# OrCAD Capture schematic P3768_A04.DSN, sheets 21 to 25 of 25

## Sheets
21 0004_SODIMM Connector 1_3: size Custom
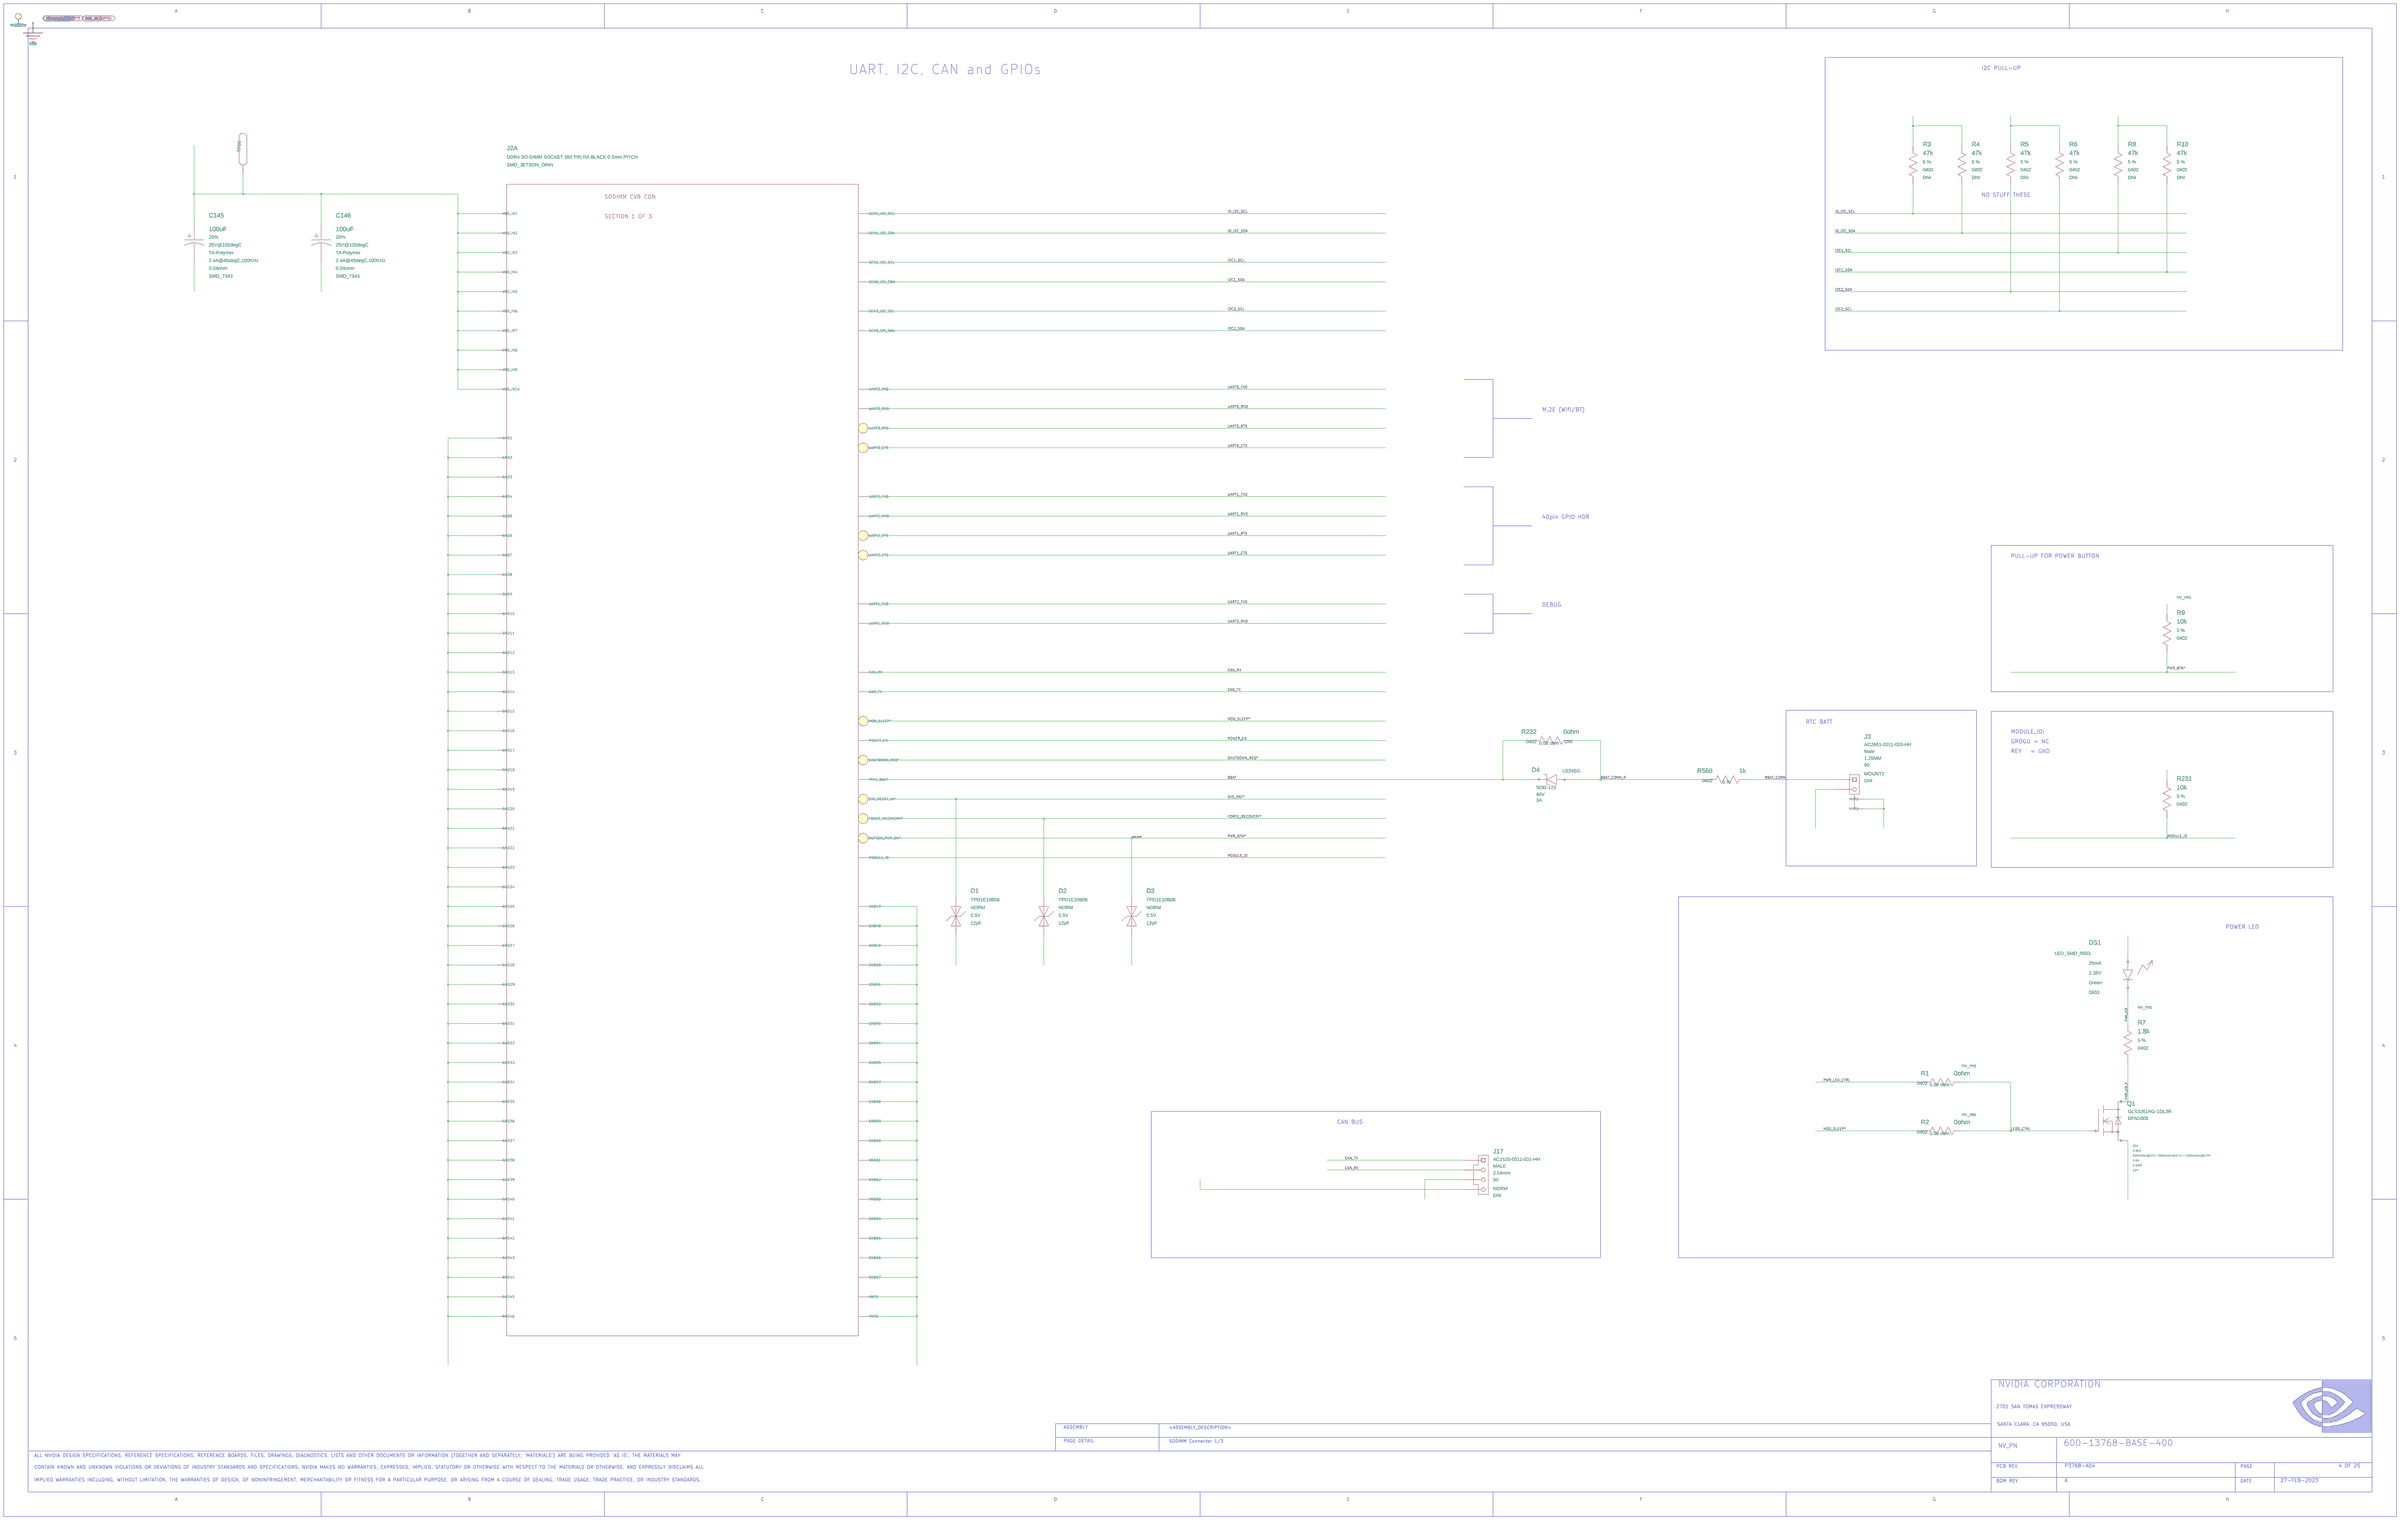
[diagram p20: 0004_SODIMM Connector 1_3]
22 0003_Power Tree
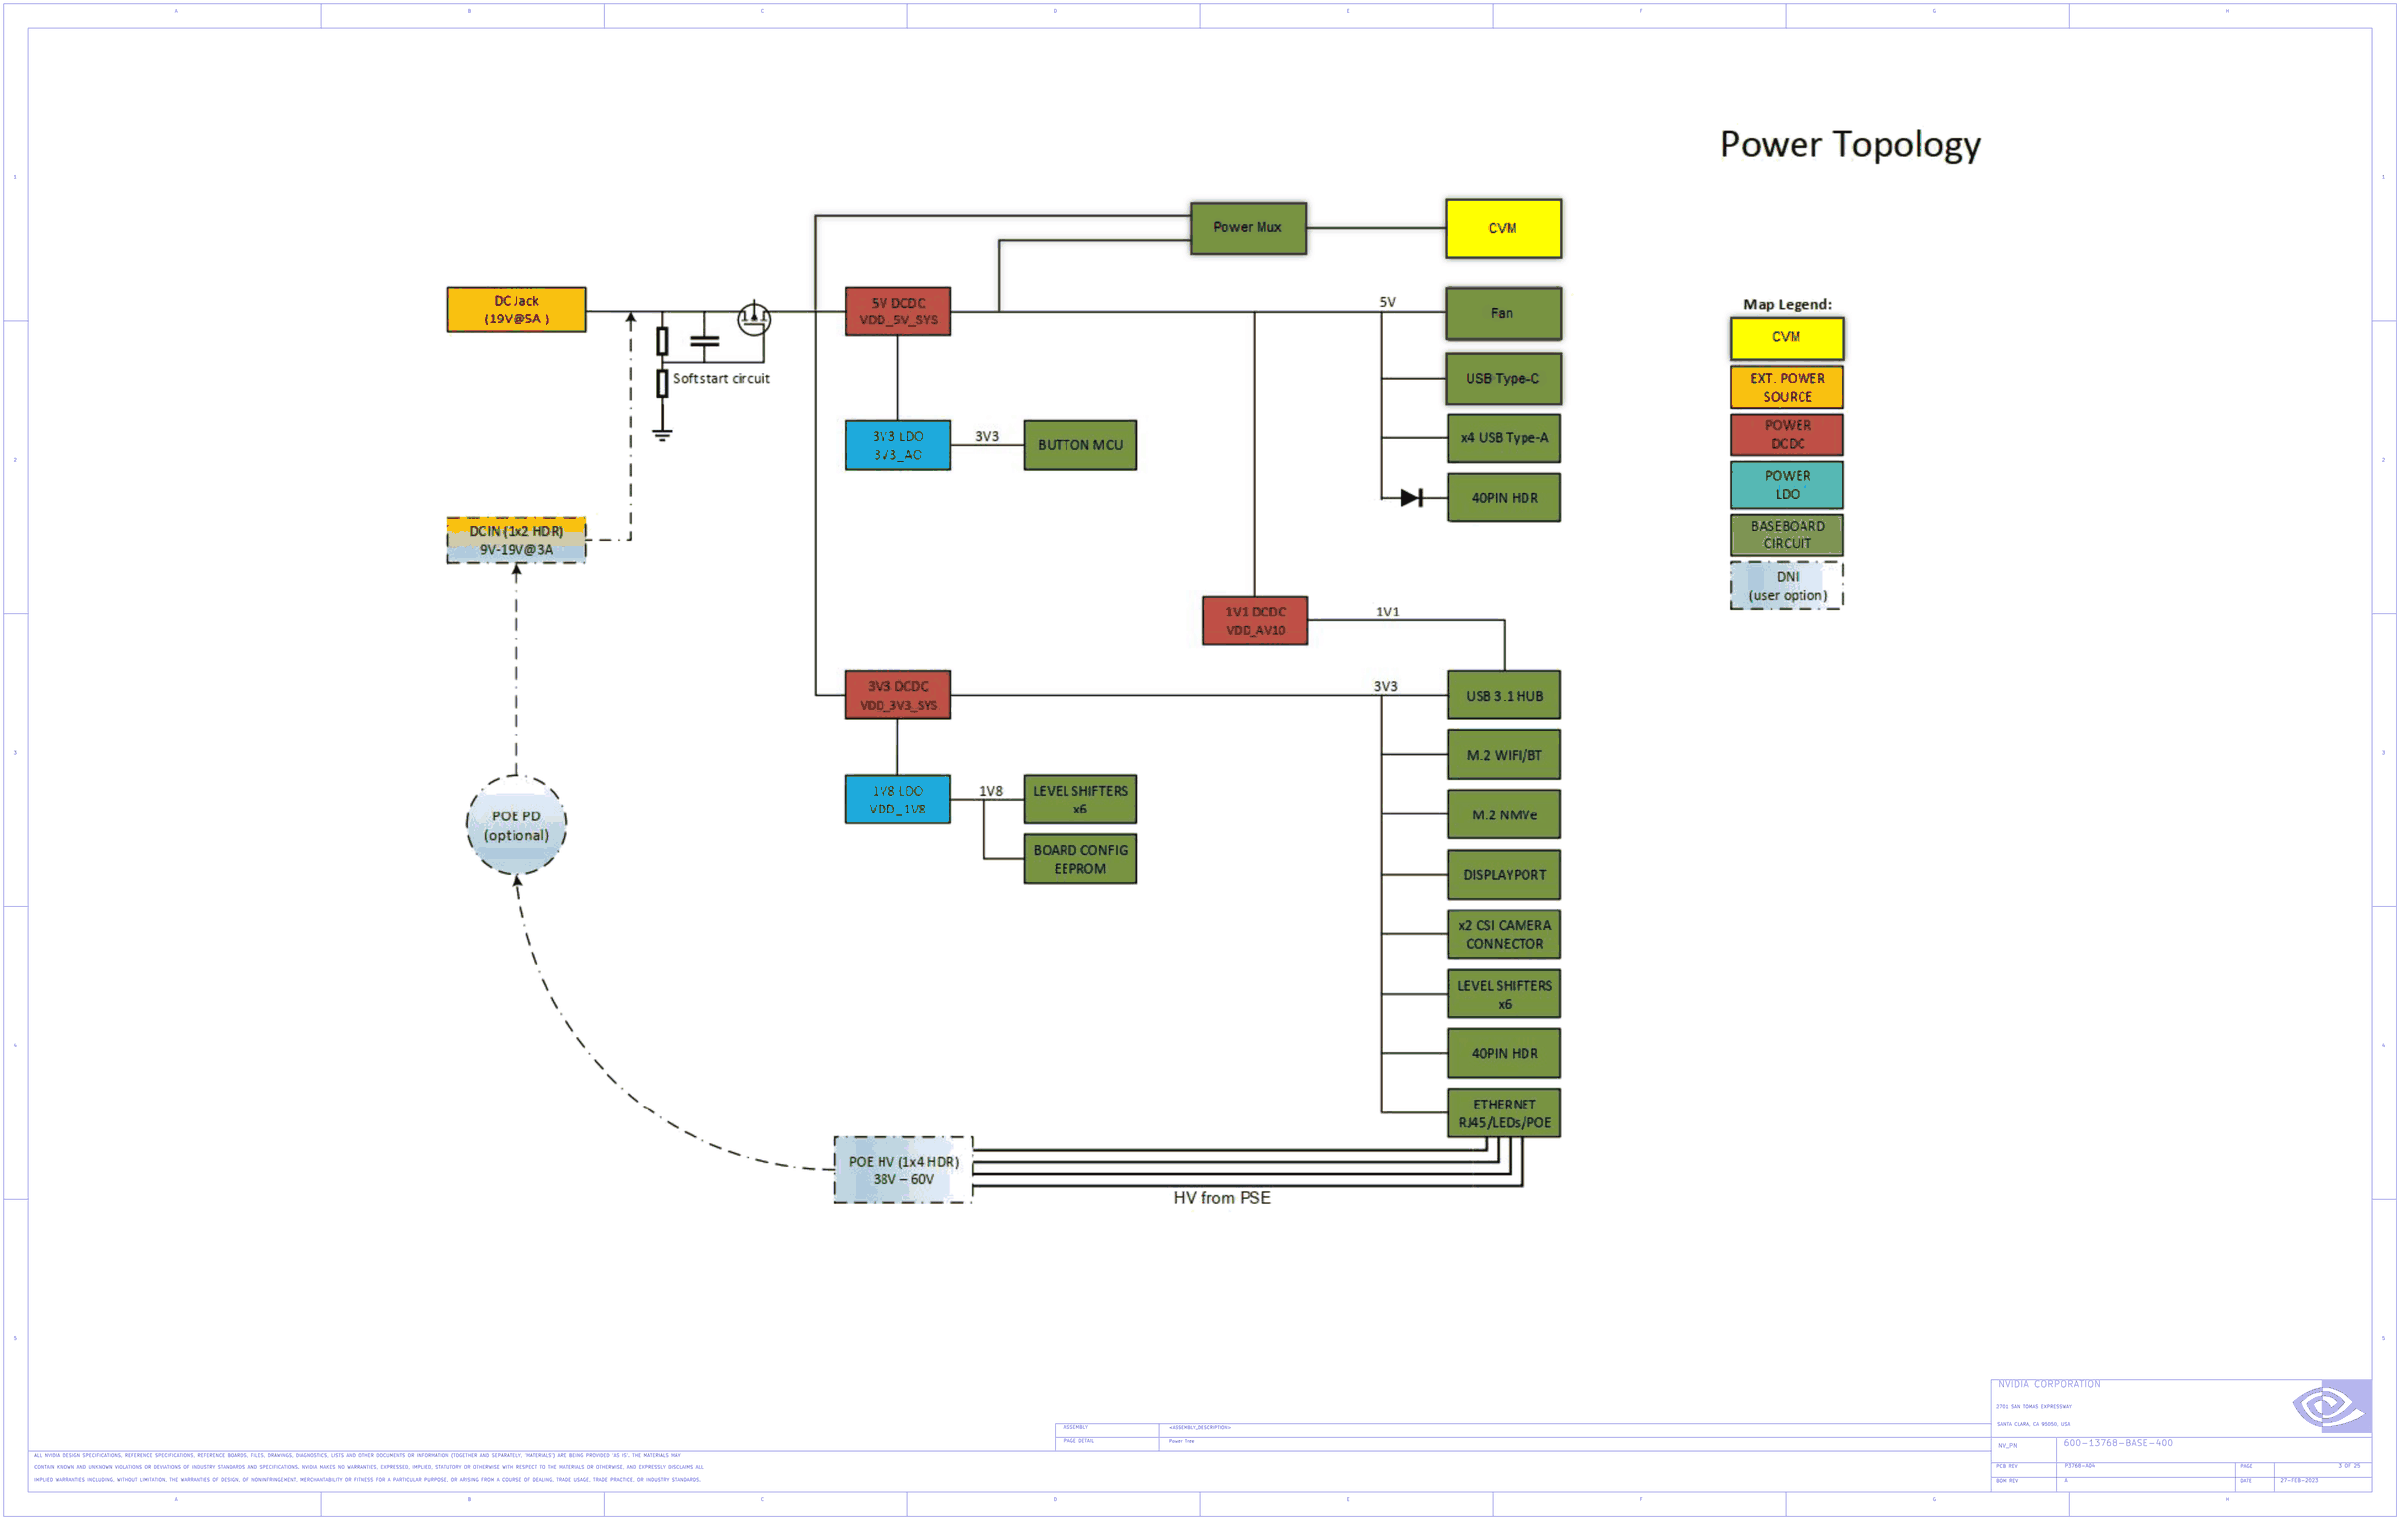
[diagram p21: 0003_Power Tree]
23 0002_Block Diagram
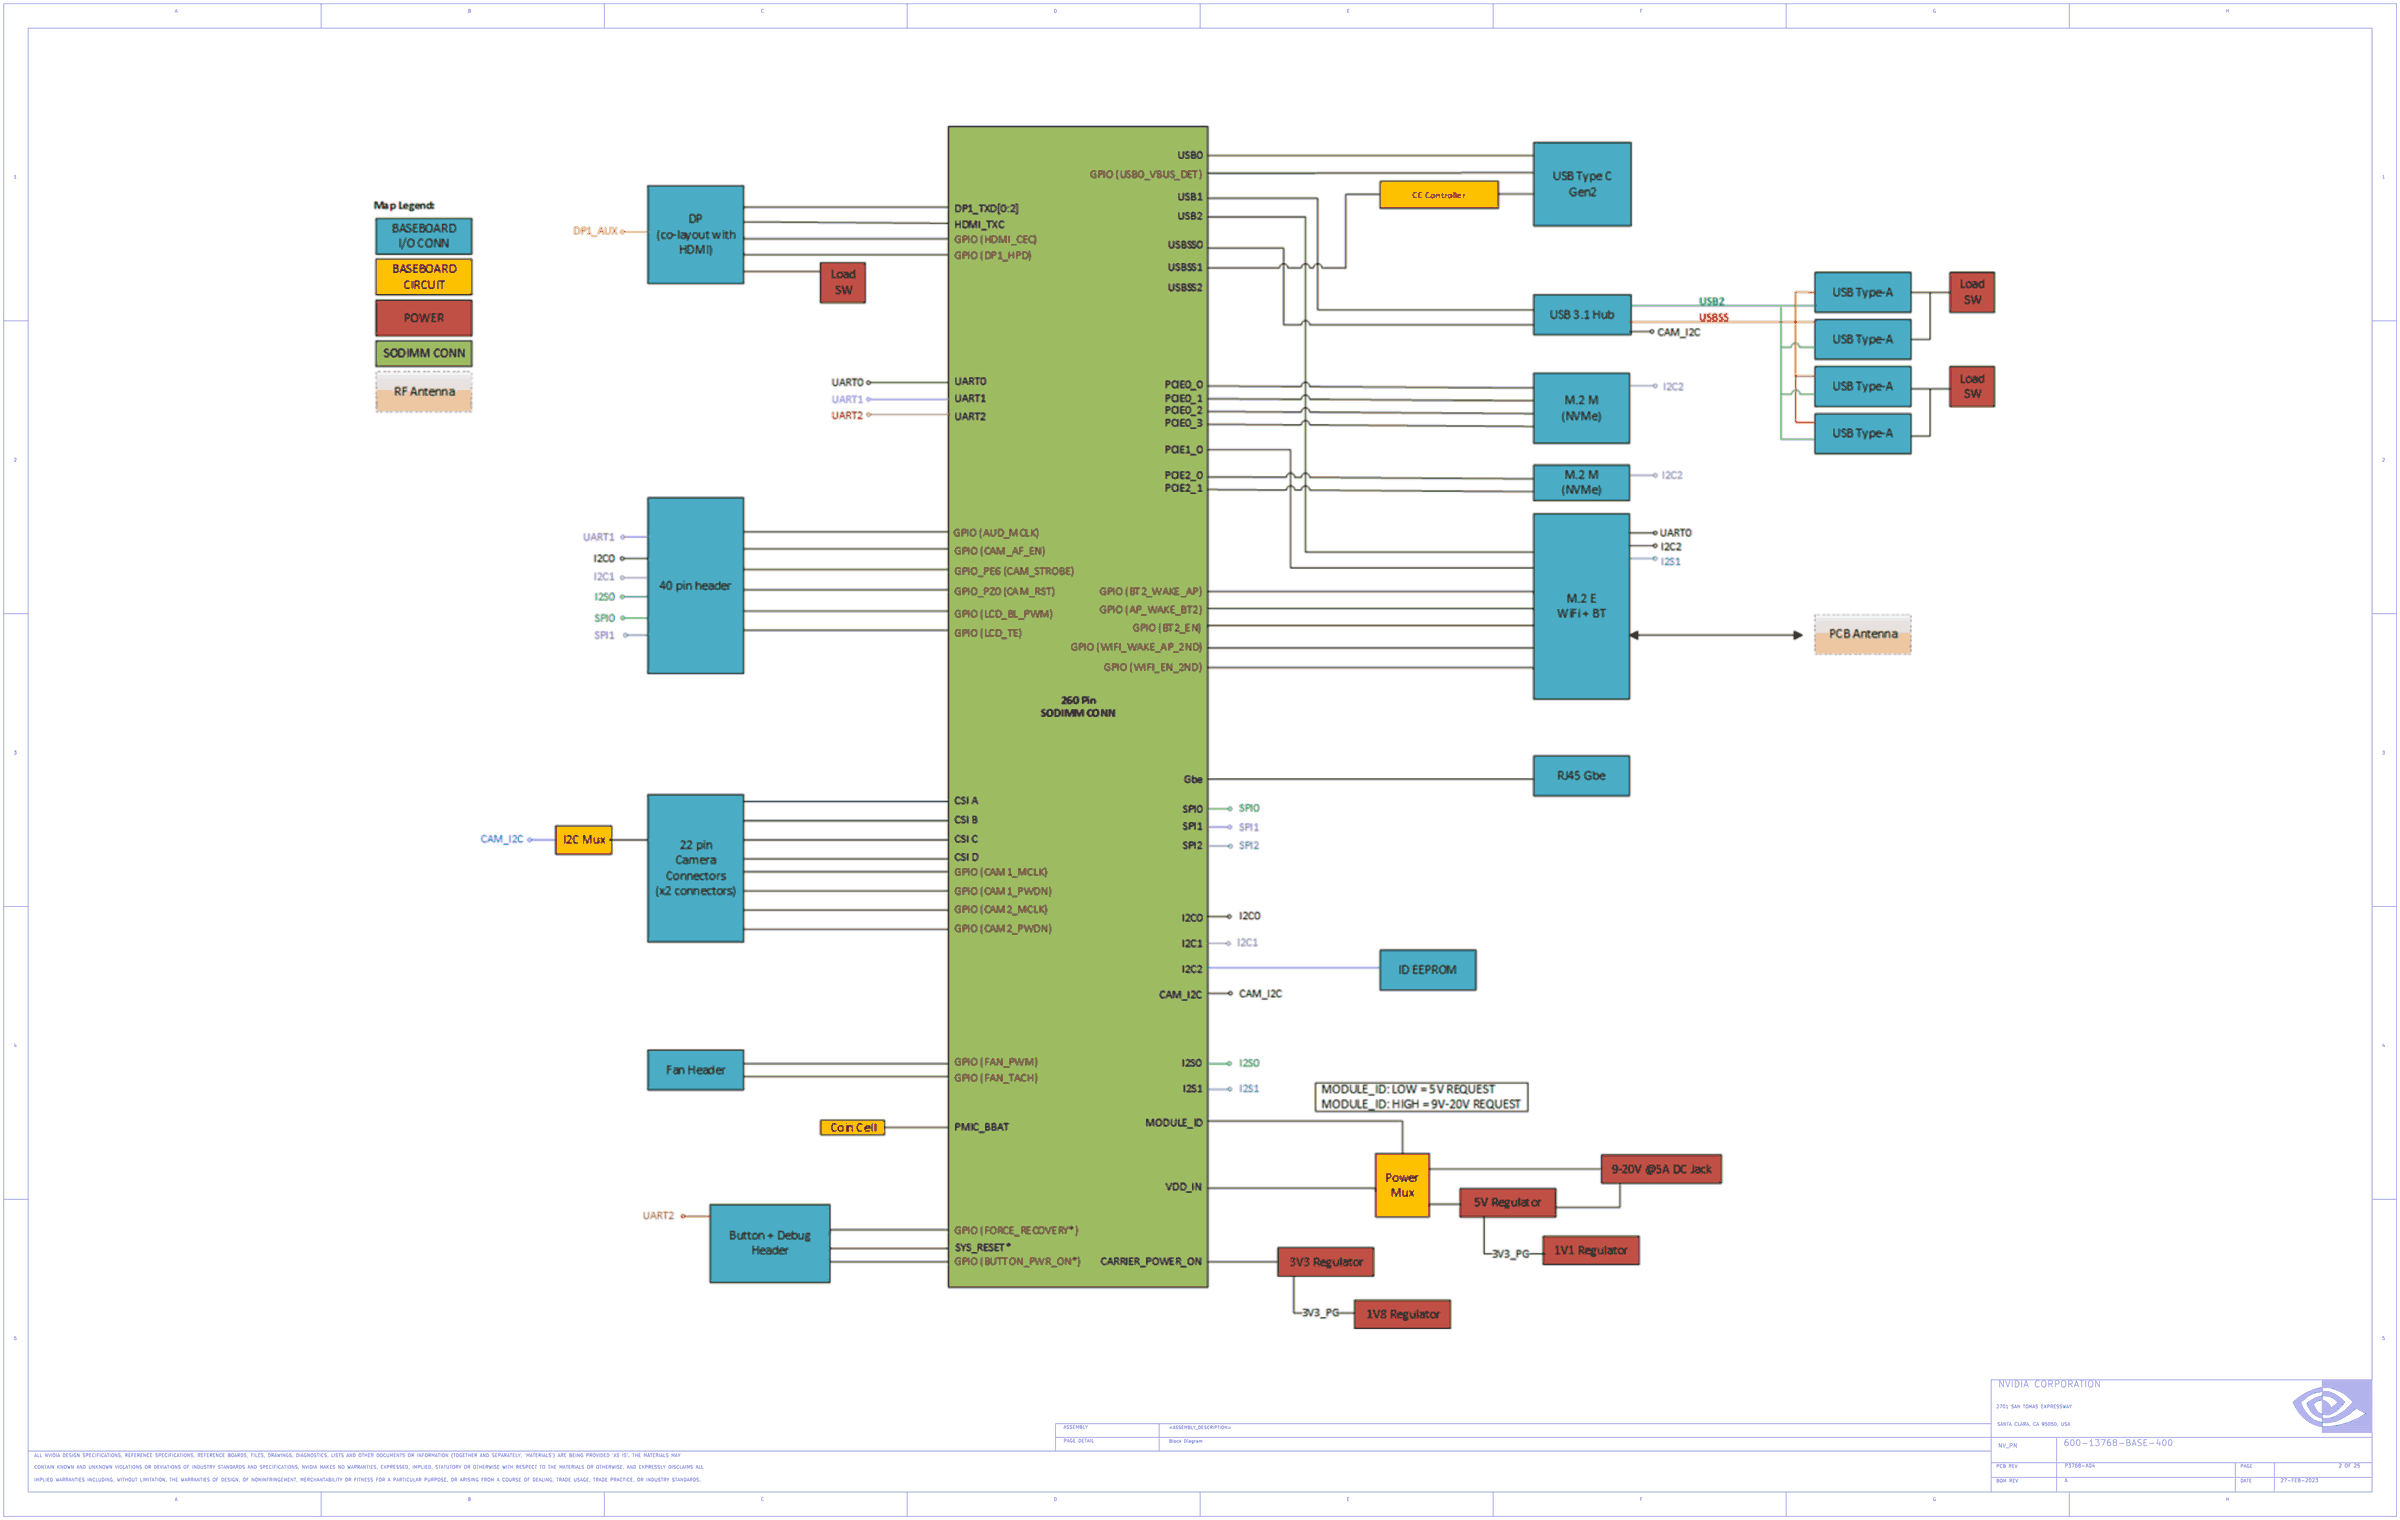
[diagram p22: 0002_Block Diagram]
24 0001_Table of Contents
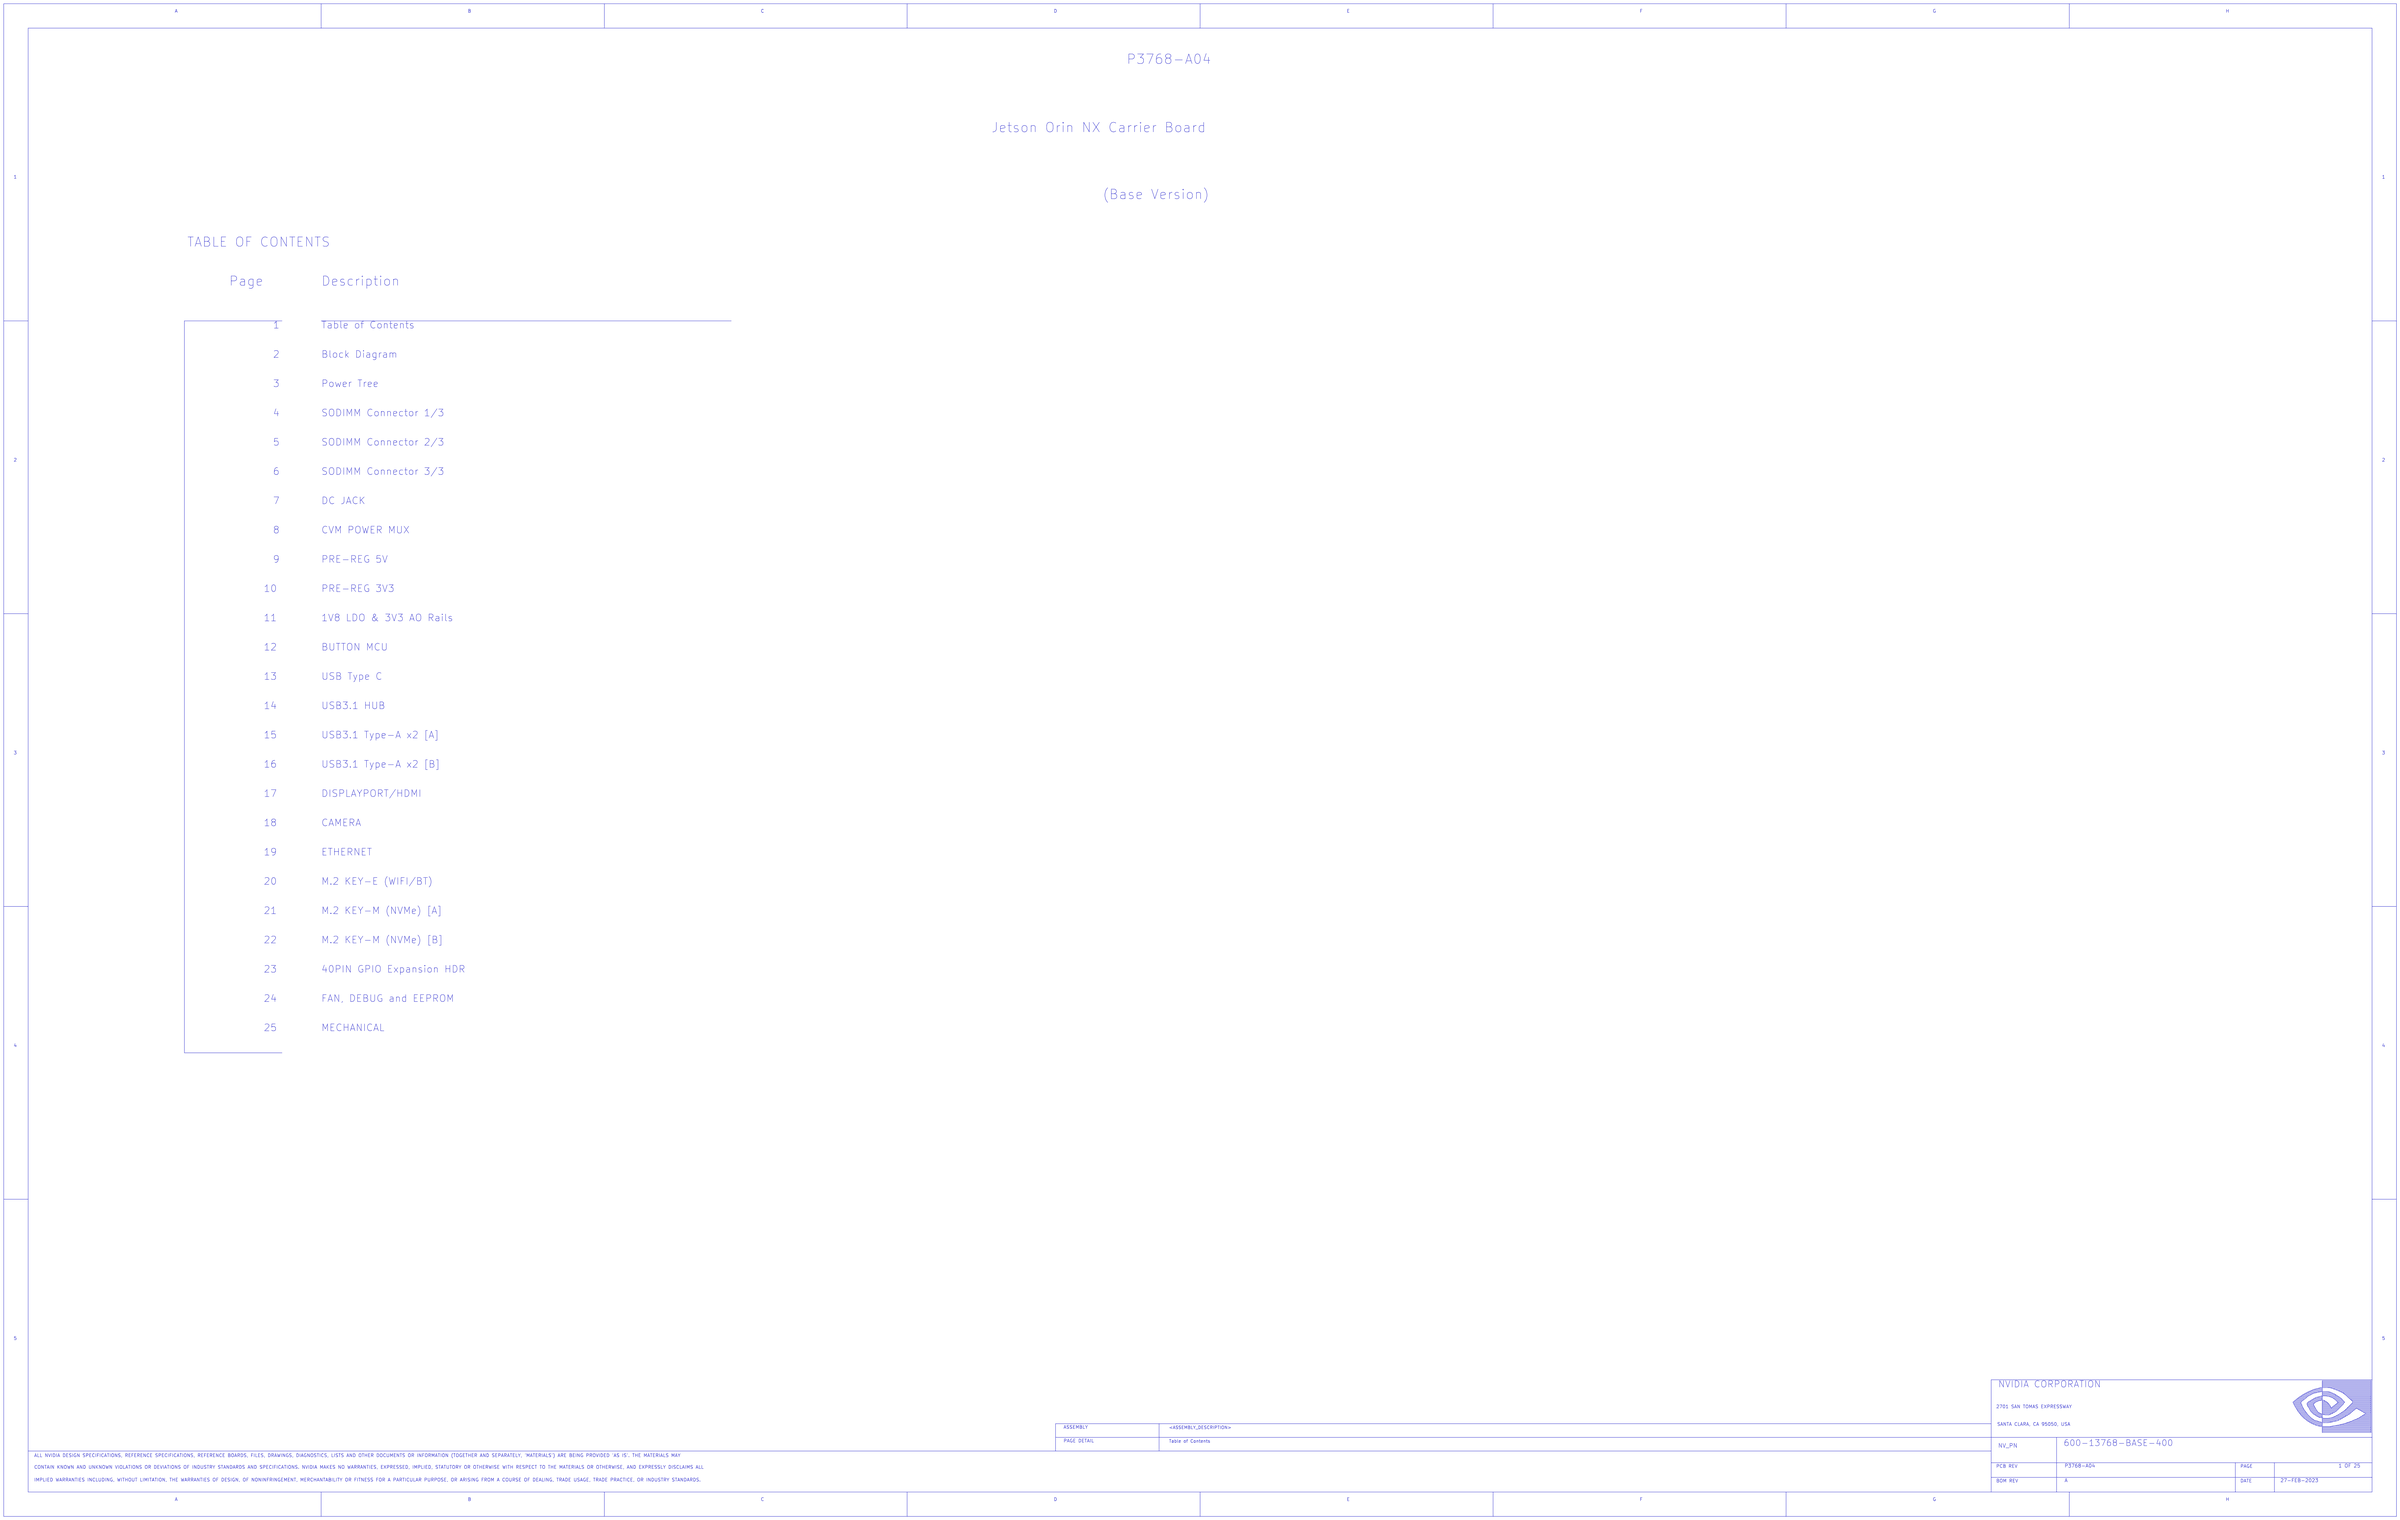
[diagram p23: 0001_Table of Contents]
25 0025_MECHANICAL: size Custom
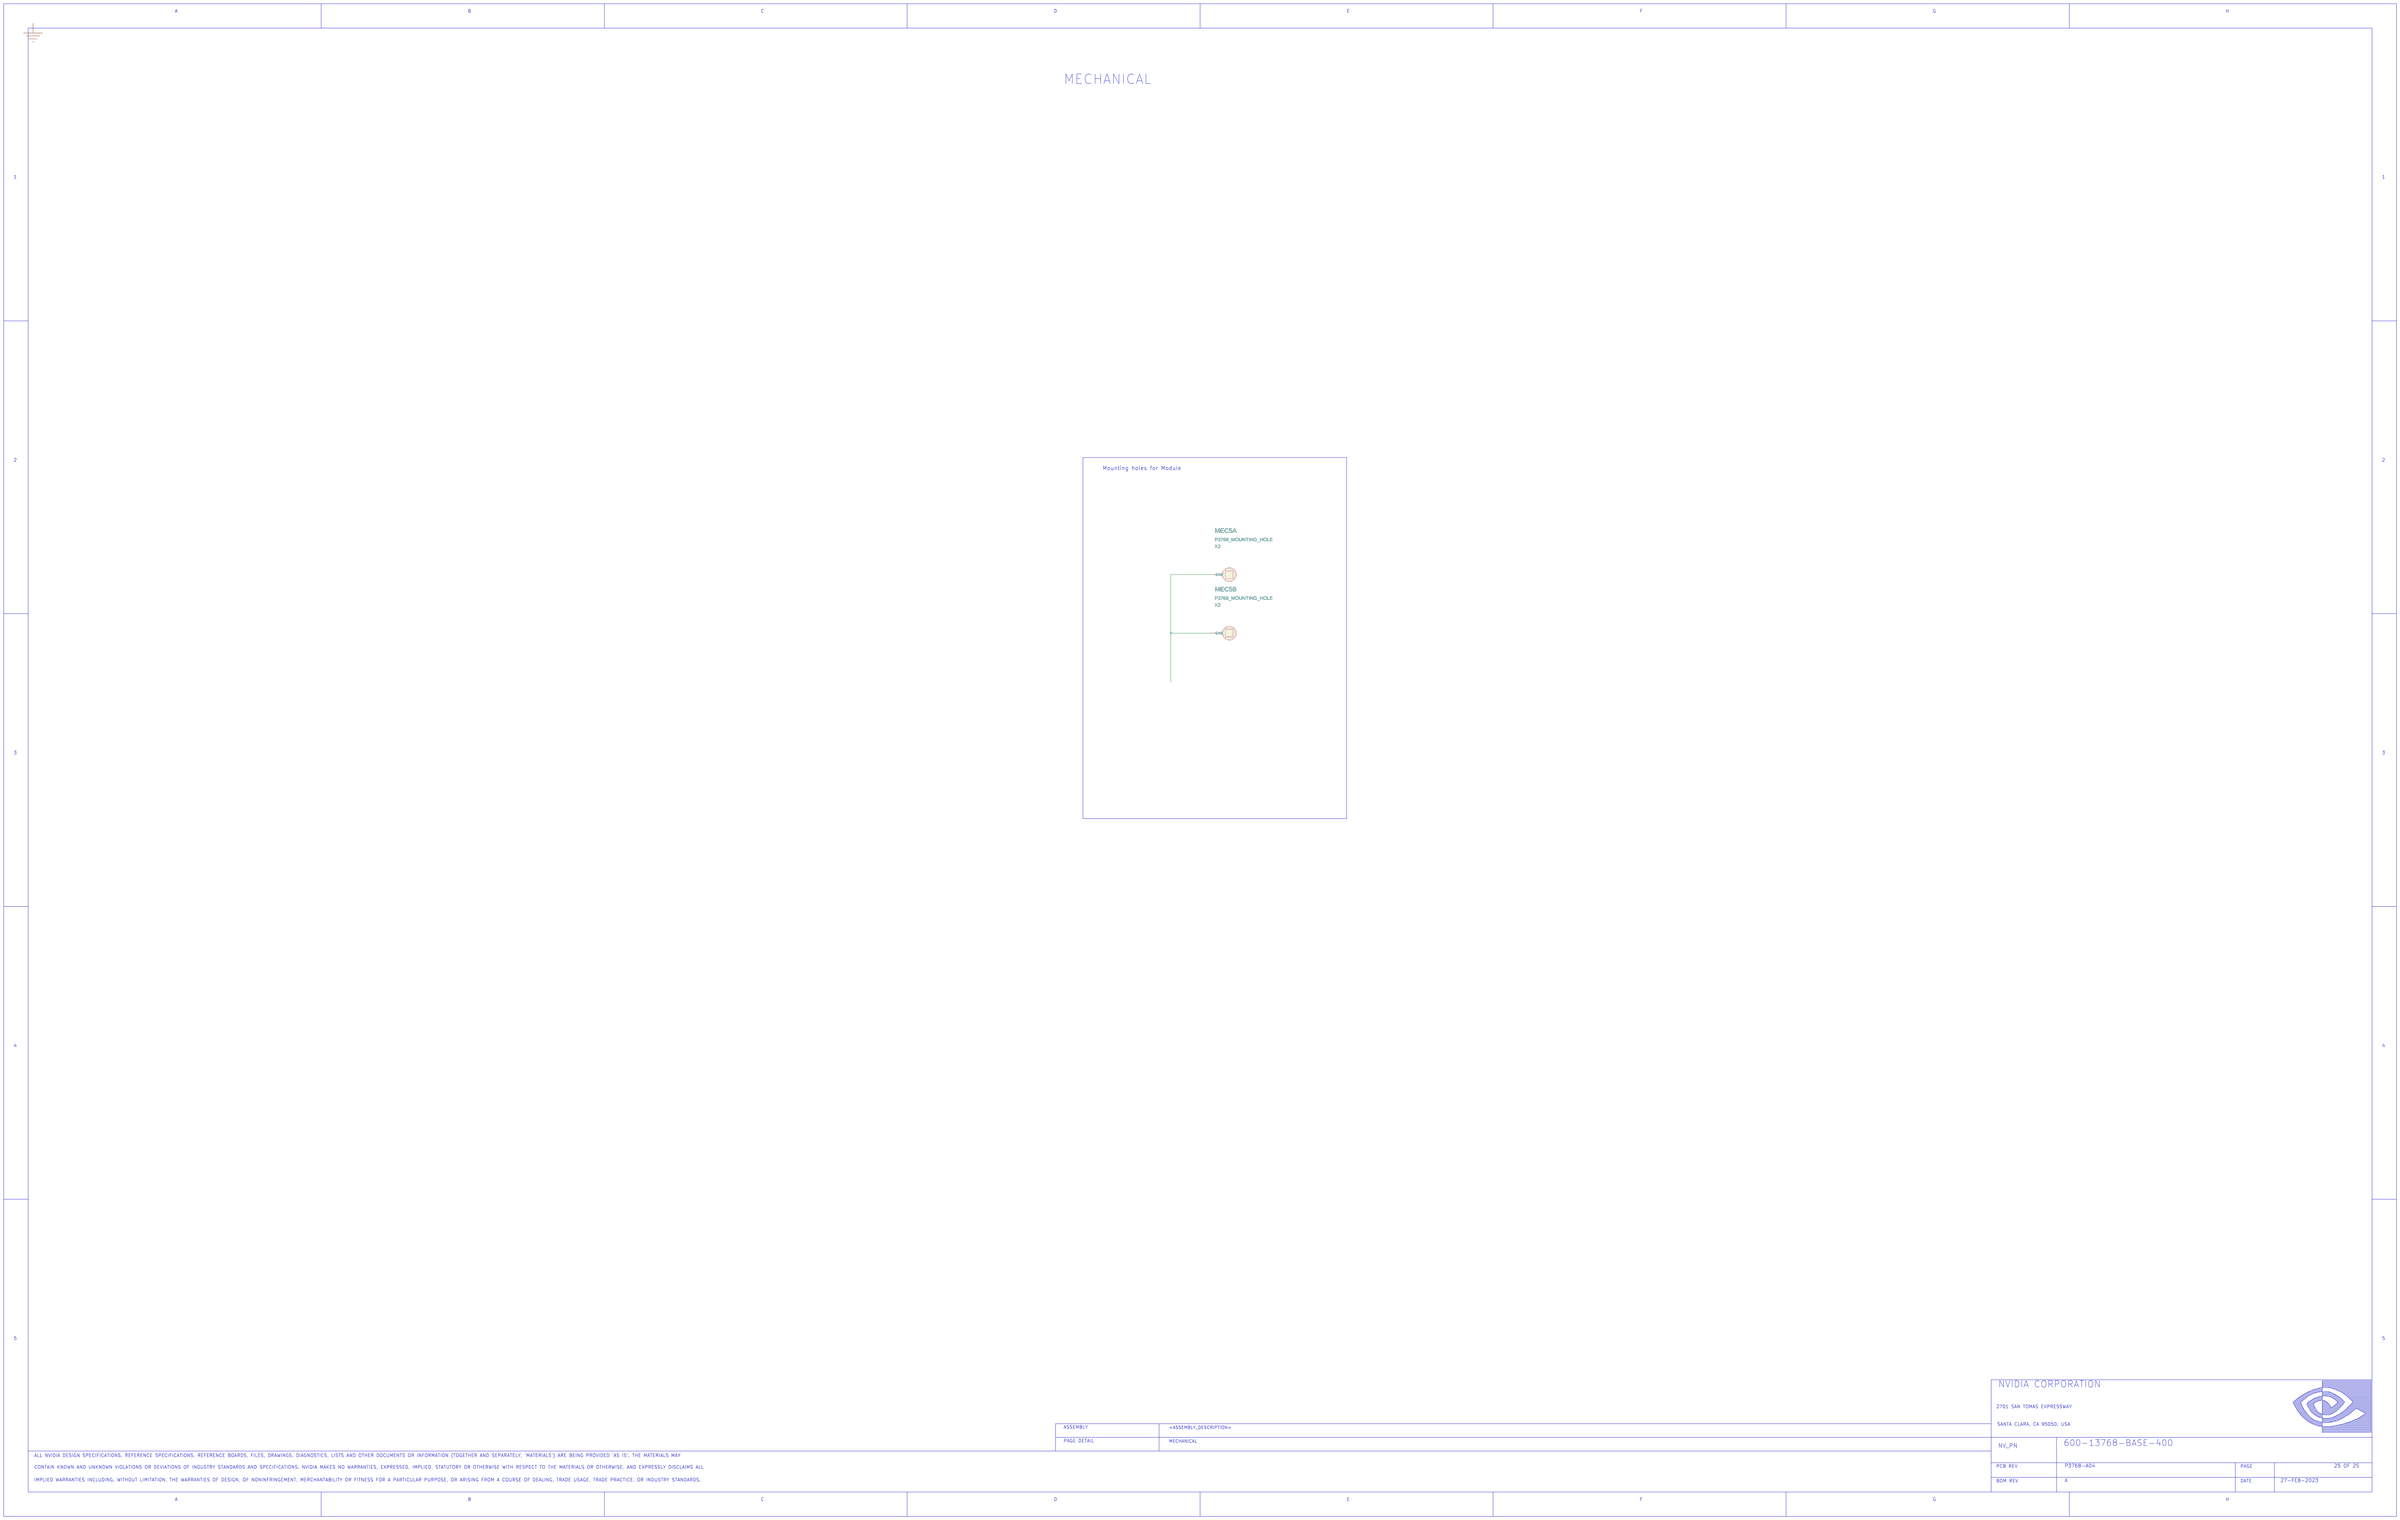
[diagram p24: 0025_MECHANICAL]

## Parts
sheet 0004_SODIMM Connector 1_3
C145  100uF  [CAP_SMD_7343]
C146  100uF  [CAP_SMD_7343]
D1  D_ESD  [DIODE_SMD_010X060]
D2  D_ESD  [DIODE_SMD_010X060]
D3  D_ESD  [DIODE_SMD_010X060]
D4  D_SCHOTTKY  [DIODE_SMD_SOD123]
DS1  LED  [LED_SMD_0603_ST]
J3  HDR_1X2  [CON_MISC_002_SMD_RA_M_P013_WTB_B]
J17  HDR_1X4  [CON_HDR_001X004_TH_RA_M_P025_B]
Q1  Q_FET_N_ENH  [DFET_003_SMD_010X006_B]
R1  0ohm  [0402]
R2  0ohm  [0402]
R3  47k  [0402]
R4  47k  [0402]
R5  47k  [0402]
R6  47k  [0402]
R7  1.8k  [0402]
R8  47k  [0402]
R9  10k  [0402]
R10  47k  [0402]
R222  0ohm  [0402]
R231  10k  [0402]
R560  1k  [0402]
TP55  LABTESTPOINT  [LTPT071C125D]
sheet 0006_SODIMM Connector 3_3
J2  CON_SODIMM_260  [CON_SODIMM_260_SMT_RA_F_P005]  (sections A,B,C)
sheet 0025_MECHANICAL
MEC5  MOUNTING_HOLE  [MECH_RECT_01000X00790_HOLES_C]  (sections A,B)

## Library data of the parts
C145 = C_POL: ASSEMBLY: CVB_CONN; CDS_LIB: discrete; CDS_PART_NAME: C_POL_SMD_7343-100UF,TA-POLYMER,20%,25V@105DEGC,0.04OHM,9.999UH,2.4A@45DEGC,100KHZ,032-0796-000; CDS_PHYS_PART_NAME: C_POL_SMD_7343-100UF,TA-POLYMER,20%,25V@105DEGC,0.04OHM,9.999UH,2.4A@45DEGC,100KHZ,032-0796-000-032-0796-000,100UF; CDS_SEC: 1; DEVICE_TYPENAME: C_POL_SMD_7343-100UFTA-POLYMER2025V105DEGC004OHM9999UH24A45DEGC100KHZ032-0796-000-032-0796-000100UF; DRAWING: @P3768_A04_LIB.P3768_A04(SCH_1):PAGE4; ESL: 9.999uH; ESR: 0.04ohm; MAT: TA-Polymer; MAX_VOLTAGE: 25V@105degC; NV_PN: 032-0796-000; PACK_TYPE: SMD_7343; PATH: I146; PHYS_PAGE: 4; RIPPLE_CURRENT: 2.4A@45degC,100KHz; ROT: 0; SEC: 1; SIGNAL_MODEL: nv_capp; TOL: 20%; VER: 1; XY: (-11150,6400)
C146 = C_POL: ASSEMBLY: CVB_CONN; CDS_LIB: discrete; CDS_PART_NAME: C_POL_SMD_7343-100UF,TA-POLYMER,20%,25V@105DEGC,0.04OHM,9.999UH,2.4A@45DEGC,100KHZ,032-0796-000; CDS_PHYS_PART_NAME: C_POL_SMD_7343-100UF,TA-POLYMER,20%,25V@105DEGC,0.04OHM,9.999UH,2.4A@45DEGC,100KHZ,032-0796-000-032-0796-000,100UF; CDS_SEC: 1; DEVICE_TYPENAME: C_POL_SMD_7343-100UFTA-POLYMER2025V105DEGC004OHM9999UH24A45DEGC100KHZ032-0796-000-032-0796-000100UF; DRAWING: @P3768_A04_LIB.P3768_A04(SCH_1):PAGE4; ESL: 9.999uH; ESR: 0.04ohm; MAT: TA-Polymer; MAX_VOLTAGE: 25V@105degC; NV_PN: 032-0796-000; PACK_TYPE: SMD_7343; PATH: I147; PHYS_PAGE: 4; RIPPLE_CURRENT: 2.4A@45degC,100KHz; ROT: 0; SEC: 1; SIGNAL_MODEL: nv_capp; TOL: 20%; VER: 1; XY: (-10500,6400)
D1 = D_ESD: ASSEMBLY: CVB_CONN; BREAKDOWN_VOLTAGE_MIN_TYP: 6V; CAPACITANCE_MAX_TYP: 12pF; CDS_LIB: discrete; CDS_PART_NAME: D_ESD_NORM-TPD1E10B06,1 LINE,BI-DIRECTIONAL,5.5V,0.1UA,6V,10V@1A,12PF,090-0243-000; CDS_PHYS_PART_NAME: D_ESD_NORM-TPD1E10B06,1 LINE,BI-DIRECTIONAL,5.5V,0.1UA,6V,10V@1A,12PF,090-0243-000-090-0243-000; CDS_SEC: 1; CLAMPING_VOLTAGE: 10V@1A; CONFIGURATION: 1 Line; DEVICE_TYPENAME: D_ESD_NORM-TPD1E10B061LINEBI-DIRECTIONAL55V01UA6V10V1A12PF090-0243-000-090-0243-000; DRAWING: @P3768_A04_LIB.P3768_A04(SCH_1):PAGE4; MAX_REVERSE_LEAKAGE_CURRENT: 0.1uA; MAX_REVERSE_VOLTAGE: 5.5V; NV_NAME: TPD1E10B06; NV_PN: 090-0243-000; PACK_TYPE: NORM; PATH: I54; PHYS_PAGE: 4; POLARITY: Bi-Directional; ROT: 0; SEC: 1; VER: 2; XY: (-7250,2950)
D2 = D_ESD: ASSEMBLY: CVB_CONN; BREAKDOWN_VOLTAGE_MIN_TYP: 6V; CAPACITANCE_MAX_TYP: 12pF; CDS_LIB: discrete; CDS_PART_NAME: D_ESD_NORM-TPD1E10B06,1 LINE,BI-DIRECTIONAL,5.5V,0.1UA,6V,10V@1A,12PF,090-0243-000; CDS_PHYS_PART_NAME: D_ESD_NORM-TPD1E10B06,1 LINE,BI-DIRECTIONAL,5.5V,0.1UA,6V,10V@1A,12PF,090-0243-000-090-0243-000; CDS_SEC: 1; CLAMPING_VOLTAGE: 10V@1A; CONFIGURATION: 1 Line; DEVICE_TYPENAME: D_ESD_NORM-TPD1E10B061LINEBI-DIRECTIONAL55V01UA6V10V1A12PF090-0243-000-090-0243-000; DRAWING: @P3768_A04_LIB.P3768_A04(SCH_1):PAGE4; MAX_REVERSE_LEAKAGE_CURRENT: 0.1uA; MAX_REVERSE_VOLTAGE: 5.5V; NV_NAME: TPD1E10B06; NV_PN: 090-0243-000; PACK_TYPE: NORM; PATH: I53; PHYS_PAGE: 4; POLARITY: Bi-Directional; ROT: 0; SEC: 1; VER: 2; XY: (-6800,2950)
D3 = D_ESD: ASSEMBLY: CVB_CONN; BREAKDOWN_VOLTAGE_MIN_TYP: 6V; CAPACITANCE_MAX_TYP: 12pF; CDS_LIB: discrete; CDS_PART_NAME: D_ESD_NORM-TPD1E10B06,1 LINE,BI-DIRECTIONAL,5.5V,0.1UA,6V,10V@1A,12PF,090-0243-000; CDS_PHYS_PART_NAME: D_ESD_NORM-TPD1E10B06,1 LINE,BI-DIRECTIONAL,5.5V,0.1UA,6V,10V@1A,12PF,090-0243-000-090-0243-000; CDS_SEC: 1; CLAMPING_VOLTAGE: 10V@1A; CONFIGURATION: 1 Line; DEVICE_TYPENAME: D_ESD_NORM-TPD1E10B061LINEBI-DIRECTIONAL55V01UA6V10V1A12PF090-0243-000-090-0243-000; DRAWING: @P3768_A04_LIB.P3768_A04(SCH_1):PAGE4; MAX_REVERSE_LEAKAGE_CURRENT: 0.1uA; MAX_REVERSE_VOLTAGE: 5.5V; NV_NAME: TPD1E10B06; NV_PN: 090-0243-000; PACK_TYPE: NORM; PATH: I51; PHYS_PAGE: 4; POLARITY: Bi-Directional; ROT: 0; SEC: 1; VER: 2; XY: (-6350,2950)
D4 = D_SCHOTTKY: ASSEMBLY: CVB_CONN; CDS_LIB: discrete; CDS_PART_NAME: D_SCHOTTKY_SOD-123-LS34SG,SINGLE,40V,25A,0.38V@1A,3A,090-0155-000; CDS_PHYS_PART_NAME: D_SCHOTTKY_SOD-123-LS34SG,SINGLE,40V,25A,0.38V@1A,3A,090-0155-000-090-0155-000; CDS_SEC: 1; CONFIGURATION: Single; CONTINUOUS_CURRENT: 3A; DEVICE_TYPENAME: D_SCHOTTKY_SOD-123-LS34SGSINGLE40V25A038V1A3A090-0155-000-090-0155-000; DRAWING: @P3768_A04_LIB.P3768_A04(SCH_1):PAGE4; FORWARD_VOLTAGE: 0.38V@1A; MAX_CURRENT: 25A; MAX_VOLTAGE: 40V; NV_NAME: LS34SG; NV_PN: 090-0155-000; PACK_TYPE: SOD-123; PATH: I42; PHYS_PAGE: 4; PLACEMENT_NOTE: bottom side of pcb near J45; ROT: 0; SEC: 1; SEC_TYPE: SOD-123; VER: 1; XY: (-4200,3650)
DS1 = LED: ASSEMBLY: POWER_LED; CDS_LIB: discrete; CDS_PART_NAME: LED_0603-LED_SMD_0603,5V,60MA,2.35V,25MA,GREEN,092-0073-000; CDS_PHYS_PART_NAME: LED_0603-LED_SMD_0603,5V,60MA,2.35V,25MA,GREEN,092-0073-000-092-0073-000; CDS_SEC: 1; CONTINUOUS_CURRENT: 25mA; DEVICE_TYPENAME: LED_0603-LED_SMD_06035V60MA235V25MAGREEN092-0073-000-092-0073-000; DRAWING: @P3768_A04_LIB.P3768_A04(SCH_1):PAGE4; FORWARD_VOLTAGE: 2.35V; MAX_CURRENT: 60mA; MAX_VOLTAGE: 5V; NV_COLOR: Green; NV_NAME: LED_SMD_0603; NV_PN: 092-0073-000; PACK_TYPE: 0603; PATH: I21; PHYS_PAGE: 4; ROT: 0; SEC: 1; VER: 1; XY: (-1250,2650)
J3 = HDR_1X2#1: ANGLE: 90; ASSEMBLY: CVB_CONN; CDS_LIB: electro_mechanic; CDS_PART_NAME: HDR_1X2_MOUNT2-AC2651-0011-003-HH,MALE,1.25MM,90,YES,NO,NO,50 V,1 A,080-1923-000; CDS_PHYS_PART_NAME: HDR_1X2_MOUNT2-AC2651-0011-003-HH,MALE,1.25MM,90,YES,NO,NO,50 V,1 A,080-1923-000-080-1923-000; CDS_SEC: 1; DEVICE_TYPENAME: HDR_1X2_MOUNT2-AC2651-0011-003-HHMALE125MM90YESNONO50V1A080-1923-000-080-1923-000; DRAWING: @P3768_A04_LIB.P3768_A04(SCH_1):PAGE4; GENDER: Male; LATCHING: NO; MAX_CURRENT: 1 A; MAX_VOLTAGE: 50 V; NV_NAME: AC2651-0011-003-HH; NV_PN: 080-1923-000; PACK_TYPE: MOUNT2; PATH: I131; PHYS_PAGE: 4; PITCH: 1.25MM; REFLOW: YES; ROT: 0; SEC: 1; SEC_TYPE: MOUNT2; SHROUDED: no; SKU: DNI; VER: 4; XY: (-2650,3650)
J17 = HDR_1X4: ANGLE: 90; ASSEMBLY: CVB_CONN; CDS_LIB: electro_mechanic; CDS_PART_NAME: HDR_1X4_NORM-AC2100-0011-001-HH,MALE,2.54MM,90,NO,NO,NO,125 V,3 A,074-0245-000; CDS_PHYS_PART_NAME: HDR_1X4_NORM-AC2100-0011-001-HH,MALE,2.54MM,90,NO,NO,NO,125 V,3 A,074-0245-000-074-0245-000; CDS_SEC: 1; DEVICE_TYPENAME: HDR_1X4_NORM-AC2100-0011-001-HHMALE254MM90NONONO125V3A074-0245-000-074-0245-000; DRAWING: @P3768_A04_LIB.P3768_A04(SCH_1):PAGE4; GENDER: MALE; LATCHING: NO; MAX_CURRENT: 3 A; MAX_VOLTAGE: 125 V; NV_NAME: AC2100-0011-001-HH; NV_PN: 074-0245-000; PACK_TYPE: NORM; PATH: I93; PHYS_PAGE: 4; PITCH: 2.54mm; REFLOW: NO; ROT: 0; SEC: 1; SHROUDED: NO; SKU: DNI; VER: 1; XY: (-4550,1700)
Q1 = Q_FET_N_ENH#1: ASSEMBLY: POWER_LED; CDS_LIB: discrete; CDS_PART_NAME: Q_FET_N_ENH_DFN1006-GLS3261NG-1DL3R,30V,600MOHM@10V / 650MOHM@4.5V / 1200MOHM@2.5V,0.95A,3.8A,12V,0.83W,0NC@10V / 0NC@4.5V / 0NC@2.5V,300-1253-000; CDS_PHYS_PART_NAME: Q_FET_N_ENH_DFN1006-GLS3261NG-1DL3R,30V,600MOHM@10V / 650MOHM@4.5V / 1200MOHM@2.5V,0.95A,3.8A,12V,0.83W,0NC@10V / 0NC@4.5V / 0B; CDS_SEC: 1; CONTINUOUS_CURRENT: 0.95A; CaptureCellPackProp: Q_FET_N_ENH##1; DEVICE_TYPENAME: Q_FET_N_ENH_DFN1006-GLS3261NG-1DL3R30V600MOHM10V650MOHM45V1200MOHM25V095A38A12V083W0NC10V0NC45V0B; DRAWING: @P3768_A04_LIB.P3768_A04(SCH_1):PAGE4; MAX_CURRENT: 3.8A; MAX_VOLTAGE: 30V; MAX_WATTAGE: 0.83W; NV_NAME: GLS3261NG-1DL3R; NV_PN: 300-1253-000; PACK_TYPE: DFN1006; PATH: I23; PHYS_PAGE: 4; Q_G: 0nC@10V / 0nC@4.5V / 0nC@2.5V; ROT: 0; R_DS_ON: 600mohm@10V / 650mohm@4.5V / 1200mohm@2.5V; SEC: 1; VER: 2; V_BE_GS: 12V; XY: (-1350,1900)
R1 = R#1: ASSEMBLY: POWER_LED; CDS_LIB: discrete; CDS_PART_NAME: R_0402-0OHM,0.05 OHM,62.5MW,195-2655-000; CDS_PHYS_PART_NAME: R_0402-0OHM,0.05 OHM,62.5MW,195-2655-000-0OHM,195-2655-000; CDS_SEC: 1; CHIPS_PART_NAME: R; DEVICE_TYPENAME: R_0402-0OHM005OHM625MW195-2655-000-0OHM195-2655-000; DRAWING: @P3768_A04_LIB.P3768_A04(SCH_1):PAGE4; MAX_WATTAGE: 62.5mW; NV_PN: 195-2655-000; PATH: I28; PHYS_PAGE: 4; PSPICETEMPLATE: X^@REFDES  %1    %2   @NV_PN; ROT: 0; SEC: 1; SIGNAL_MODEL: nv_res; TOL: 0.05 ohm; VER: 1; XY: (-2200,2100)
R2 = R#1: ASSEMBLY: POWER_LED; CDS_LIB: discrete; CDS_PART_NAME: R_0402-0OHM,0.05 OHM,62.5MW,195-2655-000; CDS_PHYS_PART_NAME: R_0402-0OHM,0.05 OHM,62.5MW,195-2655-000-0OHM,195-2655-000; CDS_SEC: 1; CHIPS_PART_NAME: R; DEVICE_TYPENAME: R_0402-0OHM005OHM625MW195-2655-000-0OHM195-2655-000; DRAWING: @P3768_A04_LIB.P3768_A04(SCH_1):PAGE4; MAX_WATTAGE: 62.5mW; NV_PN: 195-2655-000; PATH: I27; PHYS_PAGE: 4; PSPICETEMPLATE: X^@REFDES  %1    %2   @NV_PN; ROT: 0; SEC: 1; SIGNAL_MODEL: nv_res; TOL: 0.05 ohm; VER: 1; XY: (-2200,1850)
R3 = R: ASSEMBLY: CVB_CONN; CDS_LIB: discrete; CDS_PART_NAME: R_0402-47K,5 %,62.5MW,195-0599-000; CDS_PHYS_PART_NAME: R_0402-47K,5 %,62.5MW,195-0599-000-195-0599-000,47K; CDS_SEC: 1; DEVICE_TYPENAME: R_0402-47K5625MW195-0599-000-195-0599-00047K; DRAWING: @P3768_A04_LIB.P3768_A04(SCH_1):PAGE4; MAX_WATTAGE: 62.5mW; NV_PN: 195-0599-000; PATH: I16; PHYS_PAGE: 4; PSPICETEMPLATE: X^@REFDES  %1    %2   @NV_PN; ROT: 0; SEC: 1; SIGNAL_MODEL: nv_res; SKU: DNI; TOL: 5 %; VER: 2; XY: (-2350,6800)
R4 = R: ASSEMBLY: CVB_CONN; CDS_LIB: discrete; CDS_PART_NAME: R_0402-47K,5 %,62.5MW,195-0599-000; CDS_PHYS_PART_NAME: R_0402-47K,5 %,62.5MW,195-0599-000-195-0599-000,47K; CDS_SEC: 1; DEVICE_TYPENAME: R_0402-47K5625MW195-0599-000-195-0599-00047K; DRAWING: @P3768_A04_LIB.P3768_A04(SCH_1):PAGE4; MAX_WATTAGE: 62.5mW; NV_PN: 195-0599-000; PATH: I14; PHYS_PAGE: 4; PSPICETEMPLATE: X^@REFDES  %1    %2   @NV_PN; ROT: 0; SEC: 1; SIGNAL_MODEL: nv_res; SKU: DNI; TOL: 5 %; VER: 2; XY: (-2100,6800)
R5 = R: ASSEMBLY: CVB_CONN; CDS_LIB: discrete; CDS_PART_NAME: R_0402-47K,5 %,62.5MW,195-0599-000; CDS_PHYS_PART_NAME: R_0402-47K,5 %,62.5MW,195-0599-000-195-0599-000,47K; CDS_SEC: 1; DEVICE_TYPENAME: R_0402-47K5625MW195-0599-000-195-0599-00047K; DRAWING: @P3768_A04_LIB.P3768_A04(SCH_1):PAGE4; MAX_WATTAGE: 62.5mW; NV_PN: 195-0599-000; PATH: I12; PHYS_PAGE: 4; PSPICETEMPLATE: X^@REFDES  %1    %2   @NV_PN; ROT: 0; SEC: 1; SIGNAL_MODEL: nv_res; SKU: DNI; TOL: 5 %; VER: 2; XY: (-1850,6800)
R6 = R: ASSEMBLY: CVB_CONN; CDS_LIB: discrete; CDS_PART_NAME: R_0402-47K,5 %,62.5MW,195-0599-000; CDS_PHYS_PART_NAME: R_0402-47K,5 %,62.5MW,195-0599-000-195-0599-000,47K; CDS_SEC: 1; DEVICE_TYPENAME: R_0402-47K5625MW195-0599-000-195-0599-00047K; DRAWING: @P3768_A04_LIB.P3768_A04(SCH_1):PAGE4; MAX_WATTAGE: 62.5mW; NV_PN: 195-0599-000; PATH: I10; PHYS_PAGE: 4; PSPICETEMPLATE: X^@REFDES  %1    %2   @NV_PN; ROT: 0; SEC: 1; SIGNAL_MODEL: nv_res; SKU: DNI; TOL: 5 %; VER: 2; XY: (-1600,6800)
R7 = R: ASSEMBLY: POWER_LED; CDS_LIB: discrete; CDS_PART_NAME: R_0402-1.8K,5 %,62.5MW,195-0528-000; CDS_PHYS_PART_NAME: R_0402-1.8K,5 %,62.5MW,195-0528-000-1.8K,195-0528-000; CDS_SEC: 1; DEVICE_TYPENAME: R_0402-18K5625MW195-0528-000-18K195-0528-000; DRAWING: @P3768_A04_LIB.P3768_A04(SCH_1):PAGE4; MAX_WATTAGE: 62.5mW; NV_PN: 195-0528-000; PATH: I22; PHYS_PAGE: 4; PSPICETEMPLATE: X^@REFDES  %1    %2   @NV_PN; ROT: 0; SEC: 1; SIGNAL_MODEL: nv_res; TOL: 5 %; VER: 2; XY: (-1250,2300)
R8 = R: ASSEMBLY: CVB_CONN; CDS_LIB: discrete; CDS_PART_NAME: R_0402-47K,5 %,62.5MW,195-0599-000; CDS_PHYS_PART_NAME: R_0402-47K,5 %,62.5MW,195-0599-000-195-0599-000,47K; CDS_SEC: 1; DEVICE_TYPENAME: R_0402-47K5625MW195-0599-000-195-0599-00047K; DRAWING: @P3768_A04_LIB.P3768_A04(SCH_1):PAGE4; MAX_WATTAGE: 62.5mW; NV_PN: 195-0599-000; PATH: I4; PHYS_PAGE: 4; PSPICETEMPLATE: X^@REFDES  %1    %2   @NV_PN; ROT: 0; SEC: 1; SIGNAL_MODEL: nv_res; SKU: DNI; TOL: 5 %; VER: 2; XY: (-1300,6800)
R9 = R: ASSEMBLY: CVB_CONN; CDS_LIB: discrete; CDS_PART_NAME: R_0402-10K,5 %,62.5MW,195-0486-000; CDS_PHYS_PART_NAME: R_0402-10K,5 %,62.5MW,195-0486-000-10K,195-0486-000; CDS_SEC: 1; DEVICE_TYPENAME: R_0402-10K5625MW195-0486-000-10K195-0486-000; DRAWING: @P3768_A04_LIB.P3768_A04(SCH_1):PAGE4; MAX_WATTAGE: 62.5mW; NV_PN: 195-0486-000; PATH: I19; PHYS_PAGE: 4; PSPICETEMPLATE: X^@REFDES  %1    %2   @NV_PN; ROT: 0; SEC: 1; SIGNAL_MODEL: nv_res; TOL: 5 %; VER: 2; XY: (-1050,4400)
R10 = R: ASSEMBLY: CVB_CONN; CDS_LIB: discrete; CDS_PART_NAME: R_0402-47K,5 %,62.5MW,195-0599-000; CDS_PHYS_PART_NAME: R_0402-47K,5 %,62.5MW,195-0599-000-195-0599-000,47K; CDS_SEC: 1; DEVICE_TYPENAME: R_0402-47K5625MW195-0599-000-195-0599-00047K; DRAWING: @P3768_A04_LIB.P3768_A04(SCH_1):PAGE4; MAX_WATTAGE: 62.5mW; NV_PN: 195-0599-000; PATH: I2; PHYS_PAGE: 4; PSPICETEMPLATE: X^@REFDES  %1    %2   @NV_PN; ROT: 0; SEC: 1; SIGNAL_MODEL: nv_res; SKU: DNI; TOL: 5 %; VER: 2; XY: (-1050,6800)
R222 = R#1: ASSEMBLY: CVB_CONN; CDS_LIB: discrete; CDS_PART_NAME: R_0402-0OHM,0.05 OHM,62.5MW,195-2655-000; CDS_PHYS_PART_NAME: R_0402-0OHM,0.05 OHM,62.5MW,195-2655-000-0OHM,195-2655-000; CDS_SEC: 1; CHIPS_PART_NAME: R; DEVICE_TYPENAME: R_0402-0OHM005OHM625MW195-2655-000-0OHM195-2655-000; DRAWING: @P3768_A04_LIB.P3768_A04(SCH_1):PAGE4; MAX_WATTAGE: 62.5mW; NV_PN: 195-2655-000; PATH: I94; PHYS_PAGE: 4; PSPICETEMPLATE: X^@REFDES  %1    %2   @NV_PN; ROT: 0; SEC: 1; SIGNAL_MODEL: nv_res; SKU: DNI; TOL: 0.05 ohm; VER: 1; XY: (-4200,3850)
R231 = R: ASSEMBLY: CVB_CONN; CDS_LIB: discrete; CDS_PART_NAME: R_0402-10K,5 %,62.5MW,195-0486-000; CDS_PHYS_PART_NAME: R_0402-10K,5 %,62.5MW,195-0486-000-10K,195-0486-000; CDS_SEC: 1; DEVICE_TYPENAME: R_0402-10K5625MW195-0486-000-10K195-0486-000; DRAWING: @P3768_A04_LIB.P3768_A04(SCH_1):PAGE4; MAX_WATTAGE: 62.5mW; NV_PN: 195-0486-000; PATH: I158; PHYS_PAGE: 4; ROT: 0; SEC: 1; SIGNAL_MODEL: nv_res; TOL: 5 %; VER: 2; XY: (-1050,3550)
R560 = R#1: ASSEMBLY: CVB_CONN; CDS_LIB: discrete; CDS_PART_NAME: R_0402-1K,5 %,62.5MW,195-0485-000; CDS_PHYS_PART_NAME: R_0402-1K,5 %,62.5MW,195-0485-000-195-0485-000,1K; CDS_SEC: 1; CHIPS_PART_NAME: R; DEVICE_TYPENAME: R_0402-1K5625MW195-0485-000-195-0485-0001K; DRAWING: @P3768_A04_LIB.P3768_A04(SCH_1):PAGE4; MAX_WATTAGE: 62.5mW; NV_PN: 195-0485-000; PATH: I163; PHYS_PAGE: 4; ROT: 0; SEC: 1; SIGNAL_MODEL: nv_res; TOL: 5 %; VER: 1; XY: (-3300,3650)
TP55 = LABTESTPOINT#2: CDS_LIB: electro_mechanic; CDS_PART_NAME: LABTESTPOINT_B28-LABTESTPOINT; CDS_PHYS_PART_NAME: LABTESTPOINT_B28-LABTESTPOINT; CDS_SEC: 1; DEVICE_TYPENAME: LABTESTPOINT_B28-LABTESTPOINT; DRAWING: @P3768_A04_LIB.P3768_A04(SCH_1):PAGE4; PACK_TYPE: B28; PATH: I160; PHYS_PAGE: 4; ROT: 0; SEC: 1; VER: 4; XY: (-10900,6800)
J2 = CON_SODIMM_260: ANGLE: 90; ASSEMBLY: CVB_CONN; CDS_LIB: electro_mechanic; CDS_PART_NAME: CON_SODIMM_260_SMD_JETSON_ORIN-DDR4 SO-DIMM SOCKET 260 PIN RA BLACK 0.5MM PITCH,FEMALE,0.5MM,90,YES,YES,YES,NO,NO,25 V,0.5 A,080-1746-000; CDS_PHYS_PART_NAME: CON_SODIMM_260_SMD_JETSON_ORIN-DDR4 SO-DIMM SOCKET 260 PIN RA BLACK 0.5MM PITCH,FEMALE,0.5MM,90,YES,YES,YES,NO,NO,25 V,0.5 A,0B; CDS_SEC: 1; CaptureCellPackProp: CON_SODIMM_260A; DEVICE_TYPENAME: CON_SODIMM_260_SMD_JETSON_ORIN-DDR4SO-DIMMSOCKET260PINRABLACK05MMPITCHFEMALE05MM90YESYESYESNONO25V05A0B; DRAWING: @P3768_A04_LIB.P3768_A04(SCH_1):PAGE4; EMI_GROUND_TAB: NO; GENDER: FEMALE; LATCHING: YES; MAX_CURRENT: 0.5 A; MAX_VOLTAGE: 25 V; NV_NAME: DDR4 SO-DIMM SOCKET 260 PIN RA BLACK 0.5mm PITCH; NV_PN: 080-1746-000; PACK_TYPE: SMD_JETSON_ORIN; PATH: I62; PHYS_PAGE: 4; PITCH: 0.5mm; REFLOW: YES; ROT: 0; SEC: 1; SHIELDED: NO; SHROUDED: YES; VER: 10; XY: (-8650,3750); SEC_TYPE: SMD_JETSON_ORIN
MEC5 = MOUNTING_HOLE: ASSEMBLY: NONPHYSICAL; CDS_LIB: mechanic; CDS_PART_NAME: MOUNTING_HOLE_X2-P3768_MOUNTING_HOLE; CDS_PHYS_PART_NAME: MOUNTING_HOLE_X2-P3768_MOUNTING_HOLE; CDS_SEC: 1; DEVICE_TYPENAME: MOUNTING_HOLE_X2-P3768_MOUNTING_HOLE; DRAWING: @P3768_A04_LIB.P3768_A04(SCH_1):PAGE25; NV_NAME: P3768_MOUNTING_HOLE; PACK_TYPE: X2; PATH: I5; PHYS_PAGE: 25; ROT: 0; SEC: 1; SEC_TYPE: X2; VER: 1; XY: (-5850,4700)

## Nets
3V3_AO: R231.1 ; also on sheet 13 14 17
GND: C145.2 C146.2 D1.2 D2.2 D3.2 J2.1(GND1) J2.2(GND2) J2.7(GND3) J2.8(GND4) J2.13(GND5) J2.14(GND6) J2.19(GND7) J2.20(GND8) J2.25(GND9) J2.26(GND10) J2.31(GND11) J2.32(GND12) J2.37(GND13) J2.38(GND14) J2.43(GND15) J2.44(GND16) J2.49(GND17) J2.50(GND18) J2.55(GND19) J2.56(GND20) J2.61(GND21) J2.62(GND22) J2.67(GND23) J2.68(GND24) J2.73(GND25) J2.74(GND26) J2.79(GND27) J2.80(GND28) J2.85(GND29) J2.86(GND30) J2.102(GND31) J2.107(GND32) J2.113(GND33) J2.119(GND34) J2.125(GND35) J2.129(GND36) J2.132(GND37) J2.135(GND38) J2.138(GND39) J2.141(GND40) J2.144(GND41) J2.146(GND42) J2.147(GND43) J2.152(GND44) J2.153(GND45) J2.158(GND46) J2.159(GND47) J2.164(GND48) J2.165(GND49) J2.170(GND50) J2.171(GND51) J2.176(GND52) J2.177(GND53) J2.200(GND54) J2.201(GND55) J2.231(GND57) J2.241(GND58) J2.242(GND59) J2.243(GND60) J2.244(GND61) J2.245(GND62) J2.246(GND63) J2.247(GND64) J2.248(GND65) J2.249(GND66) J2.250(GND67) J2.261(MNT1) J2.262(MNT2) J3.2 J3.3(MNT1) J3.4(MNT2) J17.3 MEC5.1(GND) MEC5.2(GND) Q1.2(S) ; also on sheet 1 2 3 4 5 6 7 8 9 10 11 12 13 14 15 16 17 18 19
VDD_1V8: R5.1 R6.1 ; also on sheet 1 2 3 5 8 12 14 19
VDD_3V3_SYS: J17.4 R3.1 R4.1 R8.1 R10.1 ; also on sheet 1 2 3 4 5 6 7 8 11 12 14 15 19 20
VDD_5V_SYS: DS1.2(A) R9.1 ; also on sheet 1 2 8 9 10 11 12 13 14 15 16 17
VDD_CVM: C145.1 C146.1 J2.251(VDD_IN1) J2.252(VDD_IN2) J2.253(VDD_IN3) J2.254(VDD_IN4) J2.255(VDD_IN5) J2.256(VDD_IN6) J2.257(VDD_IN7) J2.258(VDD_IN8) J2.259(VDD_IN9) J2.260(VDD_IN10) TP55.1 ; also on sheet 13 17
BBAT: D4.1(K) J2.235(PMIC_BBAT) R222.1
BBAT_CONN: J3.1 R560.2
BBAT_CONN_R: D4.2(A) R222.2 R560.1
CAN_RX: J2.143(CAN_RX) J17.2
CAN_TX: J2.145(CAN_TX) J17.1
FORCE_RECOVERY*: D2.1 J2.214(FORCE_RECOVERY*) ; also on sheet 1
I2C1_SCL: J2.189(GEN2_I2C_SCL) R8.2 ; also on sheet 2
I2C1_SDA: J2.191(GEN2_I2C_SDA) R10.2 ; also on sheet 2
I2C2_SCL: J2.232(GEN3_I2C_SCL) R6.2 ; also on sheet 1 3 4 5
I2C2_SDA: J2.234(GEN3_I2C_SDA) R5.2 ; also on sheet 1 3 4 5
ID_I2C_SCL: J2.185(GEN1_I2C_SCL) R3.2 ; also on sheet 2 12
ID_I2C_SDA: J2.187(GEN1_I2C_SDA) R4.2 ; also on sheet 2 12
LED0_CTRL: Q1.1(G) R1.2 R2.2
MOD_SLEEP*: J2.178(MOD_SLEEP*) R2.1 ; also on sheet 1 8
MODULE_ID: J2.217(MODULE_ID) R231.2 ; also on sheet 17
POWER_EN: J2.237(POWER_EN) ; also on sheet 13
PWR_BTN*: D3.1 J2.240(BUTTON_PWR_ON*) R9.2 ; also on sheet 1 13
PWR_LED: DS1.1(K) R7.1
PWR_LED_CTRL: R1.1 ; also on sheet 1 20
PWR_LED_R: Q1.3(D) R7.2
SHUTDOWN_REQ*: J2.233(SHUTDOWN_REQ*) ; also on sheet 13
SYS_RST*: D1.1 J2.239(SYS_RESET_IN*) ; also on sheet 1 13
UART0_CTS: J2.105(UART3_CTS) ; also on sheet 5
UART0_RTS: J2.103(UART3_RTS) ; also on sheet 5
UART0_RXD: J2.101(UART3_RXD) ; also on sheet 5
UART0_TXD: J2.99(UART3_TXD) ; also on sheet 5
UART1_CTS: J2.209(UART2_CTS) ; also on sheet 2
UART1_RTS: J2.207(UART2_RTS) ; also on sheet 2
UART1_RXD: J2.205(UART2_RXD) ; also on sheet 2
UART1_TXD: J2.203(UART2_TXD) ; also on sheet 2
UART2_RXD: J2.238(UART1_RXD) ; also on sheet 1
UART2_TXD: J2.236(UART1_TXD) ; also on sheet 1

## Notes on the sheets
sheet 21
- A
- B
- C
- D
- E
- F
- G
- H
- UART, I2C, CAN and GPIOs
- I2C PULL-UP
- 1
- 1
- NO STUFF THESE
- M.2E (Wifi/BT)
- 2
- 2
- 40pin GPIO HDR
- PULL-UP FOR POWER BUTTON
- DEBUG
- RTC BATT
- MODULE_ID:
- GROGU = NC
- REY   = GND
- 3
- 3
- POWER LED
- 4
- 4
- CAN BUS
- 5
- 5
- NVIDIA CORPORATION
- 2701 SAN TOMAS EXPRESSWAY
- SANTA CLARA, CA 95050, USA
- ASSEMBLY
- <ASSEMBLY_DESCRIPTION>
- PAGE DETAIL
- SODIMM Connector 1/3
- 600-13768-BASE-400
- NV_PN
- ALL NVIDIA DESIGN SPECIFICATIONS, REFERENCE SPECIFICATIONS, REFERENCE BOARDS, FILES, DRAWINGS, DIAGNOSTICS, LISTS AND OTHER DOCUMENTS OR INFORMATION (TOGETHER AND SEPARATELY, 'MATERIALS') ARE BEING PROVIDED 'AS IS'. THE MATERIALS MAY
- P3768-A04
- 4 OF 25
- CONTAIN KNOWN AND UNKNOWN VIOLATIONS OR DEVIATIONS OF INDUSTRY STANDARDS AND SPECIFICATIONS. NVIDIA MAKES NO WARRANTIES, EXPRESSED, IMPLIED, STATUTORY OR OTHERWISE WITH RESPECT TO THE MATERIALS OR OTHERWISE, AND EXPRESSLY DISCLAIMS ALL
- PCB REV
- PAGE
- IMPLIED WARRANTIES INCLUDING, WITHOUT LIMITATION, THE WARRANTIES OF DESIGN, OF NONINFRINGEMENT, MERCHANTABILITY OR FITNESS FOR A PARTICULAR PURPOSE, OR ARISING FROM A COURSE OF DEALING, TRADE USAGE, TRADE PRACTICE, OR INDUSTRY STANDARDS.
- BOM REV
- A
- DATE
- 27-FEB-2023
- A
- B
- C
- D
- E
- F
- G
- H
sheet 22
- A
- B
- C
- D
- E
- F
- G
- H
- 1
- 1
- 2
- 2
- 3
- 3
- 4
- 4
- 5
- 5
- NVIDIA CORPORATION
- 2701 SAN TOMAS EXPRESSWAY
- SANTA CLARA, CA 95050, USA
- ASSEMBLY
- <ASSEMBLY_DESCRIPTION>
- PAGE DETAIL
- Power Tree
- 600-13768-BASE-400
- NV_PN
- ALL NVIDIA DESIGN SPECIFICATIONS, REFERENCE SPECIFICATIONS, REFERENCE BOARDS, FILES, DRAWINGS, DIAGNOSTICS, LISTS AND OTHER DOCUMENTS OR INFORMATION (TOGETHER AND SEPARATELY, 'MATERIALS') ARE BEING PROVIDED 'AS IS'. THE MATERIALS MAY
- P3768-A04
- 3 OF 25
- CONTAIN KNOWN AND UNKNOWN VIOLATIONS OR DEVIATIONS OF INDUSTRY STANDARDS AND SPECIFICATIONS. NVIDIA MAKES NO WARRANTIES, EXPRESSED, IMPLIED, STATUTORY OR OTHERWISE WITH RESPECT TO THE MATERIALS OR OTHERWISE, AND EXPRESSLY DISCLAIMS ALL
- PCB REV
- PAGE
- IMPLIED WARRANTIES INCLUDING, WITHOUT LIMITATION, THE WARRANTIES OF DESIGN, OF NONINFRINGEMENT, MERCHANTABILITY OR FITNESS FOR A PARTICULAR PURPOSE, OR ARISING FROM A COURSE OF DEALING, TRADE USAGE, TRADE PRACTICE, OR INDUSTRY STANDARDS.
- BOM REV
- A
- DATE
- 27-FEB-2023
- A
- B
- C
- D
- E
- F
- G
- H
sheet 23
- A
- B
- C
- D
- E
- F
- G
- H
- 1
- 1
- 2
- 2
- 3
- 3
- 4
- 4
- 5
- 5
- NVIDIA CORPORATION
- 2701 SAN TOMAS EXPRESSWAY
- SANTA CLARA, CA 95050, USA
- ASSEMBLY
- <ASSEMBLY_DESCRIPTION>
- PAGE DETAIL
- Block Diagram
- 600-13768-BASE-400
- NV_PN
- ALL NVIDIA DESIGN SPECIFICATIONS, REFERENCE SPECIFICATIONS, REFERENCE BOARDS, FILES, DRAWINGS, DIAGNOSTICS, LISTS AND OTHER DOCUMENTS OR INFORMATION (TOGETHER AND SEPARATELY, 'MATERIALS') ARE BEING PROVIDED 'AS IS'. THE MATERIALS MAY
- P3768-A04
- 2 OF 25
- CONTAIN KNOWN AND UNKNOWN VIOLATIONS OR DEVIATIONS OF INDUSTRY STANDARDS AND SPECIFICATIONS. NVIDIA MAKES NO WARRANTIES, EXPRESSED, IMPLIED, STATUTORY OR OTHERWISE WITH RESPECT TO THE MATERIALS OR OTHERWISE, AND EXPRESSLY DISCLAIMS ALL
- PCB REV
- PAGE
- IMPLIED WARRANTIES INCLUDING, WITHOUT LIMITATION, THE WARRANTIES OF DESIGN, OF NONINFRINGEMENT, MERCHANTABILITY OR FITNESS FOR A PARTICULAR PURPOSE, OR ARISING FROM A COURSE OF DEALING, TRADE USAGE, TRADE PRACTICE, OR INDUSTRY STANDARDS.
- BOM REV
- A
- DATE
- 27-FEB-2023
- A
- B
- C
- D
- E
- F
- G
- H
sheet 24
- A
- B
- C
- D
- E
- F
- G
- H
- P3768-A04
- Jetson Orin NX Carrier Board
- 1
- 1
- (Base Version)
- TABLE OF CONTENTS
- Page
- Description
- 1
- Table of Contents
- 2
- Block Diagram
- 3
- Power Tree
- 4
- SODIMM Connector 1/3
- 5
- SODIMM Connector 2/3
- 2
- 2
- 6
- SODIMM Connector 3/3
- 7
- DC JACK
- 8
- CVM POWER MUX
- 9
- PRE-REG 5V
- 10
- PRE-REG 3V3
- 11
- 1V8 LDO & 3V3 AO Rails
- 12
- BUTTON MCU
- 13
- USB Type C
- 14
- USB3.1 HUB
- 15
- USB3.1 Type-A x2 [A]
- 3
- 3
- 16
- USB3.1 Type-A x2 [B]
- 17
- DISPLAYPORT/HDMI
- 18
- CAMERA
- 19
- ETHERNET
- 20
- M.2 KEY-E (WIFI/BT)
- 21
- M.2 KEY-M (NVMe) [A]
- 22
- M.2 KEY-M (NVMe) [B]
- 23
- 40PIN GPIO Expansion HDR
- 24
- FAN, DEBUG and EEPROM
- 25
- MECHANICAL
- 4
- 4
- 5
- 5
- NVIDIA CORPORATION
- 2701 SAN TOMAS EXPRESSWAY
- SANTA CLARA, CA 95050, USA
- ASSEMBLY
- <ASSEMBLY_DESCRIPTION>
- PAGE DETAIL
- Table of Contents
- 600-13768-BASE-400
- NV_PN
- ALL NVIDIA DESIGN SPECIFICATIONS, REFERENCE SPECIFICATIONS, REFERENCE BOARDS, FILES, DRAWINGS, DIAGNOSTICS, LISTS AND OTHER DOCUMENTS OR INFORMATION (TOGETHER AND SEPARATELY, 'MATERIALS') ARE BEING PROVIDED 'AS IS'. THE MATERIALS MAY
- P3768-A04
- 1 OF 25
- CONTAIN KNOWN AND UNKNOWN VIOLATIONS OR DEVIATIONS OF INDUSTRY STANDARDS AND SPECIFICATIONS. NVIDIA MAKES NO WARRANTIES, EXPRESSED, IMPLIED, STATUTORY OR OTHERWISE WITH RESPECT TO THE MATERIALS OR OTHERWISE, AND EXPRESSLY DISCLAIMS ALL
- PCB REV
- PAGE
- IMPLIED WARRANTIES INCLUDING, WITHOUT LIMITATION, THE WARRANTIES OF DESIGN, OF NONINFRINGEMENT, MERCHANTABILITY OR FITNESS FOR A PARTICULAR PURPOSE, OR ARISING FROM A COURSE OF DEALING, TRADE USAGE, TRADE PRACTICE, OR INDUSTRY STANDARDS.
- BOM REV
- A
- DATE
- 27-FEB-2023
- A
- B
- C
- D
- E
- F
- G
- H
sheet 25
- A
- B
- C
- D
- E
- F
- G
- H
- MECHANICAL
- 1
- 1
- 2
- 2
- Mounting holes for Module
- 3
- 3
- 4
- 4
- 5
- 5
- NVIDIA CORPORATION
- 2701 SAN TOMAS EXPRESSWAY
- SANTA CLARA, CA 95050, USA
- ASSEMBLY
- <ASSEMBLY_DESCRIPTION>
- PAGE DETAIL
- MECHANICAL
- 600-13768-BASE-400
- NV_PN
- ALL NVIDIA DESIGN SPECIFICATIONS, REFERENCE SPECIFICATIONS, REFERENCE BOARDS, FILES, DRAWINGS, DIAGNOSTICS, LISTS AND OTHER DOCUMENTS OR INFORMATION (TOGETHER AND SEPARATELY, 'MATERIALS') ARE BEING PROVIDED 'AS IS'. THE MATERIALS MAY
- P3768-A04
- 25 OF 25
- CONTAIN KNOWN AND UNKNOWN VIOLATIONS OR DEVIATIONS OF INDUSTRY STANDARDS AND SPECIFICATIONS. NVIDIA MAKES NO WARRANTIES, EXPRESSED, IMPLIED, STATUTORY OR OTHERWISE WITH RESPECT TO THE MATERIALS OR OTHERWISE, AND EXPRESSLY DISCLAIMS ALL
- PCB REV
- PAGE
- IMPLIED WARRANTIES INCLUDING, WITHOUT LIMITATION, THE WARRANTIES OF DESIGN, OF NONINFRINGEMENT, MERCHANTABILITY OR FITNESS FOR A PARTICULAR PURPOSE, OR ARISING FROM A COURSE OF DEALING, TRADE USAGE, TRADE PRACTICE, OR INDUSTRY STANDARDS.
- BOM REV
- A
- DATE
- 27-FEB-2023
- A
- B
- C
- D
- E
- F
- G
- H
